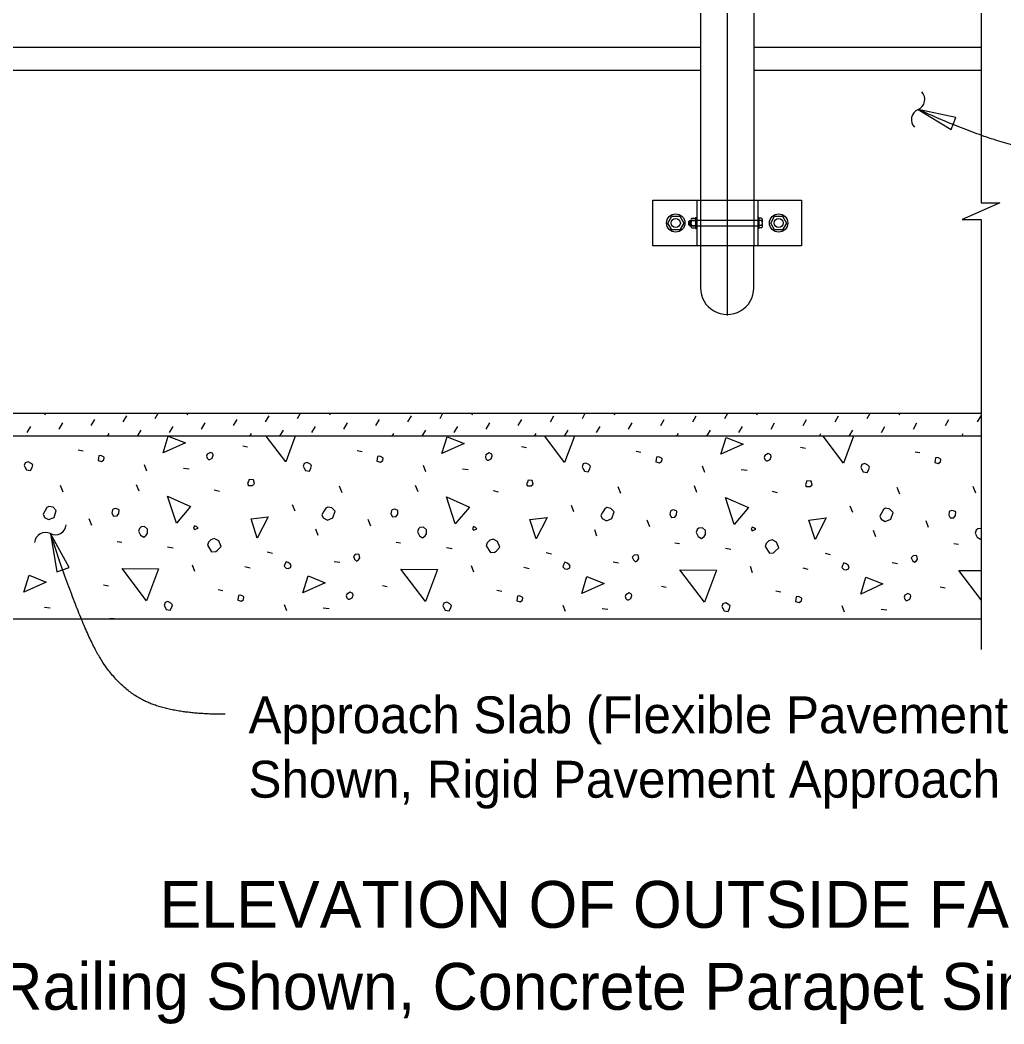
# Model space of a CAD drawing. Extents: x 0.2 to 40.8, y 0.5 to 25.7.
# Drawn here: x 10.75 to 16.13, y 10.89 to 16.37 of the extents above; entities that cross this region are included whole.
import ezdxf

# ---------------------------------------------------------------- set-up
doc = ezdxf.new("R2010")
doc.units = 0
for name, color, linetype in [('CL_Major', 7, 'Continuous'), ('Dimension', 7, 'Continuous'), ('Miscellaneous', 7, 'Continuous'), ('SteelMisc', 7, 'Continuous'), ('SteelMisc_h', 7, 'Continuous'), ('SupstrConc', 7, 'Continuous')]:
    doc.layers.add(name, color=color, linetype=linetype)

msp = doc.modelspace()

# ---------------------------------------------------------------- linework, layer by layer
at = {"layer": 'CL_Major'}
msp.add_line((14.615, 25.0052), (14.615, 14.7584), dxfattribs=at)
at = {"layer": 'Dimension'}
msp.add_lwpolyline([(16.002, 17.2246), (16.002, 15.3737), (16.1053, 15.3737), (16.002, 15.3287), (15.8987, 15.2837), (16.002, 15.2837), (16.002, 12.9339)], dxfattribs=at)
for points in [[(15.6583, 15.8852), (15.8392, 15.7761), (15.865, 15.8418)], [(10.9179, 13.5672), (10.9525, 13.3589), (11.0192, 13.3819)]]:
    msp.add_lwpolyline(points, close=True, dxfattribs=at)
for centre, start, end in [((15.6351, 15.9394), 292.7091, 44.4364), ((15.6811, 15.8294), 112.7091, 224.4364), ((10.944, 13.6201), 243.2317, 354.9589), ((10.8904, 13.5137), 63.2317, 174.9589)]:
    msp.add_arc(centre, 0.0596, start, end, dxfattribs=at)
for points in [[(16.9853, 15.6282), (16.9154, 15.6282), (16.2159, 15.6282), (15.6583, 15.8852)], [(11.8715, 12.5794), (11.6062, 12.5794), (11.3076, 12.7039), (11.092, 13.036), (10.9179, 13.5672)]]:
    msp.add_open_spline(points, degree=2, dxfattribs=at)
at = {"layer": 'Miscellaneous'}
for p, q in [((14.4075, 15.2575), (14.4075, 15.2696)), ((14.4132, 15.2575), (14.4132, 15.2696)), ((10.8876, 14.2162), (10.8924, 14.2245)), ((11.3154, 14.1773), (11.3349, 14.2109)), ((11.4904, 14.1967), (11.5065, 14.2245)), ((11.6655, 14.2162), (11.6703, 14.2245)), ((12.0933, 14.1773), (12.1127, 14.2109)), ((12.2683, 14.1967), (12.2843, 14.2245)), ((12.4433, 14.2162), (12.4481, 14.2245)), ((12.8711, 14.1773), (12.8905, 14.2109)), ((13.0461, 14.1967), (13.0621, 14.2245)), ((13.2211, 14.2162), (13.2259, 14.2245)), ((13.6489, 14.1773), (13.6683, 14.2109)), ((13.8239, 14.1967), (13.84, 14.2245)), ((13.9989, 14.2162), (14.0037, 14.2245)), ((14.4267, 14.1773), (14.4462, 14.2109)), ((14.6017, 14.1967), (14.6178, 14.2245)), ((14.7767, 14.2162), (14.7815, 14.2245)), ((15.2045, 14.1773), (15.224, 14.2109)), ((15.3795, 14.1967), (15.3956, 14.2245)), ((15.5545, 14.2162), (15.5593, 14.2245)), ((15.9823, 14.1773), (16.0018, 14.2109)), ((10.9654, 14.1384), (10.9849, 14.172)), ((11.1404, 14.1579), (11.1599, 14.1914)), ((11.7432, 14.1384), (11.7627, 14.172)), ((11.9182, 14.1579), (11.9377, 14.1914)), ((12.5211, 14.1384), (12.5405, 14.172)), ((12.6961, 14.1579), (12.7155, 14.1914)), ((13.2989, 14.1384), (13.3183, 14.172)), ((13.4739, 14.1579), (13.4933, 14.1914)), ((14.0767, 14.1384), (14.0961, 14.172)), ((14.2517, 14.1579), (14.2711, 14.1914)), ((14.8545, 14.1384), (14.874, 14.172)), ((15.0295, 14.1579), (15.049, 14.1914)), ((15.6323, 14.1384), (15.6518, 14.172)), ((15.8073, 14.1579), (15.8268, 14.1914)), ((10.7904, 14.119), (10.8099, 14.1526)), ((11.2295, 14.0995), (11.2377, 14.1137)), ((11.3932, 14.0995), (11.4127, 14.1331)), ((11.5682, 14.119), (11.5877, 14.1526)), ((12.0073, 14.0995), (12.0155, 14.1137)), ((12.171, 14.0995), (12.1905, 14.1331)), ((12.346, 14.119), (12.3655, 14.1526)), ((12.7851, 14.0995), (12.7933, 14.1137)), ((12.9489, 14.0995), (12.9683, 14.1331)), ((13.1239, 14.119), (13.1433, 14.1526)), ((13.5629, 14.0995), (13.5711, 14.1137)), ((13.7267, 14.0995), (13.7461, 14.1331)), ((13.9017, 14.119), (13.9211, 14.1526)), ((14.3407, 14.0995), (14.3489, 14.1137)), ((14.5045, 14.0995), (14.5239, 14.1331)), ((14.6795, 14.119), (14.6989, 14.1526)), ((15.1186, 14.0995), (15.1267, 14.1137)), ((15.2823, 14.0995), (15.3018, 14.1331)), ((15.4573, 14.119), (15.4768, 14.1526)), ((15.8964, 14.0995), (15.9046, 14.1137)), ((11.9679, 14.0465), (11.9945, 14.0412)), ((11.0699, 14.0253), (11.0964, 14.02)), ((12.5937, 14.0217), (12.6202, 14.0164)), ((13.4917, 14.043), (13.5183, 14.0376)), ((14.1175, 14.0182), (14.1441, 14.0129)), ((15.0156, 14.0394), (15.0421, 14.0341)), ((15.6414, 14.0147), (15.6679, 14.0094)), ((11.4447, 13.9086), (11.4323, 13.9422)), ((12.9685, 13.9051), (12.9561, 13.9387)), ((14.4923, 13.9015), (14.4799, 13.9351)), ((11.6444, 13.9245), (11.6763, 13.921)), ((13.1682, 13.921), (13.2001, 13.9174)), ((14.6921, 13.9174), (14.7239, 13.9139)), ((10.9868, 13.7937), (10.9727, 13.8291)), ((11.4022, 13.799), (11.3881, 13.8344)), ((12.5106, 13.7902), (12.4965, 13.8255)), ((12.9261, 13.7955), (12.9119, 13.8308)), ((14.4499, 13.7919), (14.4357, 13.8273)), ((11.8124, 13.8061), (11.8407, 13.799)), ((13.3362, 13.8025), (13.3645, 13.7955)), ((14.0345, 13.7866), (14.0203, 13.822)), ((14.86, 13.799), (14.8883, 13.7919)), ((15.5583, 13.7831), (15.5441, 13.8184)), ((15.9737, 13.7884), (15.9596, 13.8237)), ((12.2543, 13.6894), (12.2402, 13.7248)), ((13.7781, 13.6859), (13.764, 13.7212)), ((15.3019, 13.6823), (15.2878, 13.7177)), ((11.1442, 13.6116), (11.13, 13.647)), ((12.668, 13.6081), (12.6538, 13.6434)), ((14.1918, 13.6045), (14.1776, 13.6399)), ((15.7156, 13.601), (15.7015, 13.6364)), ((12.3798, 13.5568), (12.3675, 13.5904)), ((13.9036, 13.5533), (13.8913, 13.5869)), ((15.4275, 13.5497), (15.4151, 13.5833)), ((11.282, 13.5232), (11.3068, 13.5197)), ((12.8059, 13.5197), (12.8306, 13.5162)), ((14.3297, 13.5162), (14.3544, 13.5126)), ((15.8535, 13.5126), (15.8782, 13.5091)), ((11.5578, 13.4949), (11.5879, 13.4896)), ((12.1023, 13.4667), (12.1306, 13.4596)), ((13.0816, 13.4914), (13.1117, 13.4861)), ((13.6261, 13.4631), (13.6544, 13.4561)), ((14.6054, 13.4879), (14.6355, 13.4826)), ((15.1499, 13.4596), (15.1782, 13.4525)), ((11.7063, 13.3606), (11.6939, 13.3942)), ((11.9803, 13.3871), (12.0086, 13.38)), ((12.4682, 13.4154), (12.4983, 13.4101)), ((13.2301, 13.3571), (13.2177, 13.3906)), ((13.992, 13.4119), (14.0221, 13.4066)), ((14.7539, 13.3535), (14.7416, 13.3871)), ((15.5158, 13.4083), (15.5459, 13.403)), ((13.5041, 13.3836), (13.5324, 13.3765)), ((15.0279, 13.38), (15.0562, 13.373)), ((11.2078, 13.2863), (11.2343, 13.281)), ((12.7316, 13.2828), (12.7581, 13.2775)), ((14.2554, 13.2793), (14.2819, 13.274)), ((15.7792, 13.2757), (15.8058, 13.2704)), ((11.8336, 13.2616), (11.8601, 13.2563)), ((13.3574, 13.2581), (13.3839, 13.2528)), ((14.8812, 13.2545), (14.9077, 13.2492)), ((12.2084, 13.1449), (12.196, 13.1785)), ((13.7322, 13.1414), (13.7198, 13.175)), ((15.256, 13.1379), (15.2436, 13.1714)), ((10.8843, 13.1644), (10.9161, 13.1608)), ((12.4081, 13.1608), (12.4399, 13.1573)), ((13.9319, 13.1573), (13.9637, 13.1538)), ((15.4557, 13.1538), (15.4876, 13.1502))]:
    msp.add_line(p, q, dxfattribs=at)
for points in [[(11.5331, 14.0076), (11.5613, 14.0995), (11.655, 14.0624), (11.5331, 14.0076)], [(12.203, 13.9599), (12.0969, 14.0995)], [(12.2552, 14.0995), (12.203, 13.9599)], [(13.7269, 13.9563), (13.618, 14.0995)], [(13.7804, 14.0995), (13.7269, 13.9563)], [(15.2507, 13.9528), (15.1392, 14.0995)], [(15.3055, 14.0995), (15.2507, 13.9528)], [(13.0569, 14.0041), (13.0852, 14.096), (13.1789, 14.0589), (13.0569, 14.0041)], [(14.5807, 14.0005), (14.609, 14.0925), (14.7027, 14.0553), (14.5807, 14.0005)], [(11.1777, 13.9669), (11.1972, 13.9616), (11.2096, 13.9705), (11.2113, 13.9828), (11.2078, 13.9864), (11.1937, 13.9935), (11.1813, 13.9917), (11.1795, 13.9793), (11.1777, 13.9669)], [(11.7806, 13.9722), (11.7876, 13.9722), (11.8018, 13.9793), (11.8071, 13.9952), (11.8053, 14.0041), (11.7912, 14.0111), (11.7735, 14.0005), (11.7699, 13.9899), (11.7735, 13.9793), (11.7806, 13.9722)], [(12.7016, 13.9634), (12.721, 13.9581), (12.7334, 13.9669), (12.7351, 13.9793), (12.7316, 13.9828), (12.7175, 13.9899), (12.7051, 13.9882), (12.7033, 13.9758), (12.7016, 13.9634)], [(13.3044, 13.9687), (13.3114, 13.9687), (13.3256, 13.9758), (13.3309, 13.9917), (13.3291, 14.0005), (13.315, 14.0076), (13.2973, 13.997), (13.2938, 13.9864), (13.2973, 13.9758), (13.3044, 13.9687)], [(14.8282, 13.9652), (14.8353, 13.9652), (14.8494, 13.9722), (14.8547, 13.9882), (14.8529, 13.997), (14.8388, 14.0041), (14.8211, 13.9935), (14.8176, 13.9828), (14.8211, 13.9722), (14.8282, 13.9652)], [(10.7782, 13.9316), (10.7871, 13.9157), (10.8083, 13.9121), (10.8171, 13.928), (10.8207, 13.9422), (10.8118, 13.951), (10.7959, 13.9599), (10.78, 13.9546), (10.7747, 13.9387), (10.7782, 13.9316)], [(12.302, 13.928), (12.3109, 13.9121), (12.3321, 13.9086), (12.3409, 13.9245), (12.3445, 13.9387), (12.3356, 13.9475), (12.3197, 13.9563), (12.3038, 13.951), (12.2985, 13.9351), (12.302, 13.928)], [(13.8259, 13.9245), (13.8347, 13.9086), (13.8559, 13.9051), (13.8647, 13.921), (13.8683, 13.9351), (13.8594, 13.944), (13.8435, 13.9528), (13.8276, 13.9475), (13.8223, 13.9316), (13.8259, 13.9245)], [(14.2254, 13.9599), (14.2448, 13.9546), (14.2572, 13.9634), (14.259, 13.9758), (14.2554, 13.9793), (14.2413, 13.9864), (14.2289, 13.9846), (14.2271, 13.9722), (14.2254, 13.9599)], [(15.3497, 13.921), (15.3585, 13.9051), (15.3797, 13.9015), (15.3886, 13.9174), (15.3921, 13.9316), (15.3833, 13.9404), (15.3674, 13.9493), (15.3514, 13.944), (15.3461, 13.928), (15.3497, 13.921)], [(15.7492, 13.9563), (15.7686, 13.951), (15.781, 13.9599), (15.7828, 13.9722), (15.7792, 13.9758), (15.7651, 13.9828), (15.7527, 13.9811), (15.751, 13.9687), (15.7492, 13.9563)], [(11.9998, 13.8308), (12.021, 13.8308), (12.0316, 13.8414), (12.0263, 13.8609), (12.0033, 13.8626), (11.9998, 13.852), (11.9945, 13.8432), (11.9998, 13.8308), (11.9962, 13.8344)], [(13.5236, 13.8273), (13.5448, 13.8273), (13.5554, 13.8379), (13.5501, 13.8573), (13.5271, 13.8591), (13.5236, 13.8485), (13.5183, 13.8397), (13.5236, 13.8273), (13.52, 13.8308)], [(15.0474, 13.8237), (15.0686, 13.8237), (15.0792, 13.8344), (15.0739, 13.8538), (15.0509, 13.8556), (15.0474, 13.845), (15.0421, 13.8361), (15.0474, 13.8237), (15.0438, 13.8273)], [(11.6055, 13.624), (11.5578, 13.7707), (11.6833, 13.7159), (11.6055, 13.624)], [(10.8843, 13.6558), (10.9073, 13.6434), (10.9373, 13.6558), (10.9497, 13.6929), (10.932, 13.7106), (10.909, 13.7159), (10.8984, 13.7088), (10.8861, 13.6894), (10.8772, 13.6735), (10.8843, 13.6558)], [(13.1294, 13.6205), (13.0816, 13.7672), (13.2071, 13.7124), (13.1294, 13.6205)], [(14.6532, 13.6169), (14.6054, 13.7636), (14.731, 13.7088), (14.6532, 13.6169)], [(11.2538, 13.6788), (11.2626, 13.6629), (11.282, 13.6647), (11.2909, 13.677), (11.2926, 13.6965), (11.2803, 13.7018), (11.2714, 13.7035), (11.2608, 13.7), (11.2573, 13.6965), (11.2538, 13.6788)], [(12.4081, 13.6523), (12.4311, 13.6399), (12.4611, 13.6523), (12.4735, 13.6894), (12.4558, 13.7071), (12.4329, 13.7124), (12.4223, 13.7053), (12.4099, 13.6859), (12.401, 13.67), (12.4081, 13.6523)], [(12.7776, 13.6753), (12.7864, 13.6593), (12.8059, 13.6611), (12.8147, 13.6735), (12.8165, 13.6929), (12.8041, 13.6982), (12.7952, 13.7), (12.7846, 13.6965), (12.7811, 13.6929), (12.7776, 13.6753)], [(13.9319, 13.6487), (13.9549, 13.6364), (13.985, 13.6487), (13.9973, 13.6859), (13.9797, 13.7035), (13.9567, 13.7088), (13.9461, 13.7018), (13.9337, 13.6823), (13.9249, 13.6664), (13.9319, 13.6487)], [(14.3014, 13.6717), (14.3102, 13.6558), (14.3297, 13.6576), (14.3385, 13.67), (14.3403, 13.6894), (14.3279, 13.6947), (14.3191, 13.6965), (14.3085, 13.6929), (14.3049, 13.6894), (14.3014, 13.6717)], [(15.4557, 13.6452), (15.4787, 13.6328), (15.5088, 13.6452), (15.5211, 13.6823), (15.5035, 13.7), (15.4805, 13.7053), (15.4699, 13.6982), (15.4575, 13.6788), (15.4487, 13.6629), (15.4557, 13.6452)], [(15.8252, 13.6682), (15.834, 13.6523), (15.8535, 13.654), (15.8623, 13.6664), (15.8641, 13.6859), (15.8517, 13.6912), (15.8429, 13.6929), (15.8323, 13.6894), (15.8287, 13.6859), (15.8252, 13.6682)], [(11.3987, 13.5798), (11.4093, 13.5586), (11.427, 13.548), (11.4411, 13.5586), (11.4482, 13.5692), (11.4482, 13.5904), (11.4323, 13.6063), (11.4129, 13.6045), (11.404, 13.5957), (11.3987, 13.5798)], [(11.7045, 13.5886), (11.724, 13.5975), (11.7169, 13.6045), (11.7045, 13.6098), (11.6992, 13.5975), (11.7045, 13.5886)], [(12.0475, 13.5427), (12.0139, 13.647), (12.1076, 13.6593), (12.0475, 13.5427)], [(13.2284, 13.5851), (13.2478, 13.5939), (13.2407, 13.601), (13.2284, 13.6063), (13.223, 13.5939), (13.2284, 13.5851)], [(13.5713, 13.5391), (13.5377, 13.6434), (13.6314, 13.6558), (13.5713, 13.5391)], [(15.0951, 13.5356), (15.0615, 13.6399), (15.1552, 13.6523), (15.0951, 13.5356)], [(12.9225, 13.5763), (12.9331, 13.555), (12.9508, 13.5444), (12.965, 13.555), (12.972, 13.5657), (12.972, 13.5869), (12.9561, 13.6028), (12.9367, 13.601), (12.9278, 13.5922), (12.9225, 13.5763)], [(14.4463, 13.5727), (14.457, 13.5515), (14.4746, 13.5409), (14.4888, 13.5515), (14.4958, 13.5621), (14.4958, 13.5833), (14.4799, 13.5992), (14.4605, 13.5975), (14.4516, 13.5886), (14.4463, 13.5727)], [(14.7522, 13.5816), (14.7716, 13.5904), (14.7645, 13.5975), (14.7522, 13.6028), (14.7469, 13.5904), (14.7522, 13.5816)], [(16.002, 13.5955), (15.9843, 13.5939), (15.9755, 13.5851), (15.9702, 13.5692)], [(15.9702, 13.5692), (15.9808, 13.548), (15.9984, 13.5374), (16.002, 13.54)], [(11.7752, 13.5038), (11.7982, 13.4667), (11.8212, 13.4684), (11.83, 13.4773), (11.8495, 13.4967), (11.8371, 13.5268), (11.8124, 13.5409), (11.7947, 13.5338), (11.7806, 13.5197), (11.7752, 13.5038)], [(13.2991, 13.5002), (13.322, 13.4631), (13.345, 13.4649), (13.3539, 13.4737), (13.3733, 13.4932), (13.3609, 13.5232), (13.3362, 13.5374), (13.3185, 13.5303), (13.3044, 13.5162), (13.2991, 13.5002)], [(14.8229, 13.4967), (14.8459, 13.4596), (14.8688, 13.4614), (14.8777, 13.4702), (14.8971, 13.4896), (14.8848, 13.5197), (14.86, 13.5338), (14.8423, 13.5268), (14.8282, 13.5126), (14.8229, 13.4967)], [(12.5796, 13.4278), (12.5902, 13.4172), (12.6008, 13.4242), (12.6079, 13.4348), (12.6043, 13.4525), (12.5955, 13.4543), (12.5831, 13.4525), (12.5725, 13.4419), (12.5796, 13.4278)], [(14.1034, 13.4242), (14.114, 13.4136), (14.1246, 13.4207), (14.1317, 13.4313), (14.1281, 13.449), (14.1193, 13.4508), (14.1069, 13.449), (14.0963, 13.4384), (14.1034, 13.4242)], [(15.6272, 13.4207), (15.6378, 13.4101), (15.6484, 13.4172), (15.6555, 13.4278), (15.652, 13.4454), (15.6431, 13.4472), (15.6307, 13.4454), (15.6201, 13.4348), (15.6272, 13.4207)], [(12.2048, 13.3783), (12.2172, 13.3765), (12.2296, 13.3818), (12.2331, 13.3924), (12.2278, 13.4013), (12.2172, 13.4083), (12.2048, 13.4136), (12.1977, 13.3995), (12.1942, 13.3889), (12.2048, 13.3783)], [(13.7286, 13.3747), (13.741, 13.373), (13.7534, 13.3783), (13.7569, 13.3889), (13.7516, 13.3977), (13.741, 13.4048), (13.7286, 13.4101), (13.7216, 13.3959), (13.718, 13.3853), (13.7286, 13.3747)], [(15.2524, 13.3712), (15.2648, 13.3694), (15.2772, 13.3747), (15.2807, 13.3853), (15.2754, 13.3942), (15.2648, 13.4013), (15.2524, 13.4066), (15.2454, 13.3924), (15.2418, 13.3818), (15.2524, 13.3712)], [(10.7729, 13.2475), (10.8012, 13.3394), (10.8949, 13.3023), (10.7729, 13.2475)], [(11.4429, 13.1997), (11.3086, 13.3765), (11.5083, 13.3747), (11.4429, 13.1997)], [(12.2967, 13.2439), (12.325, 13.3358), (12.4187, 13.2987), (12.2967, 13.2439)], [(12.9667, 13.1962), (12.8324, 13.373), (13.0321, 13.3712), (12.9667, 13.1962)], [(13.8206, 13.2404), (13.8488, 13.3323), (13.9425, 13.2952), (13.8206, 13.2404)], [(14.4905, 13.1927), (14.3562, 13.3694), (14.5559, 13.3677), (14.4905, 13.1927)], [(16.002, 13.2054), (15.88, 13.3659), (16.002, 13.3648)], [(15.3444, 13.2369), (15.3727, 13.3288), (15.4663, 13.2917), (15.3444, 13.2369)], [(11.9414, 13.2033), (11.9609, 13.198), (11.9732, 13.2068), (11.975, 13.2192), (11.9715, 13.2227), (11.9573, 13.2298), (11.945, 13.228), (11.9432, 13.2156), (11.9414, 13.2033)], [(12.5442, 13.2086), (12.5513, 13.2086), (12.5654, 13.2156), (12.5707, 13.2315), (12.569, 13.2404), (12.5548, 13.2475), (12.5372, 13.2369), (12.5336, 13.2262), (12.5372, 13.2156), (12.5442, 13.2086)], [(13.4652, 13.1997), (13.4847, 13.1944), (13.4971, 13.2033), (13.4988, 13.2156), (13.4953, 13.2192), (13.4811, 13.2262), (13.4688, 13.2245), (13.467, 13.2121), (13.4652, 13.1997)], [(14.068, 13.205), (14.0751, 13.205), (14.0893, 13.2121), (14.0946, 13.228), (14.0928, 13.2369), (14.0786, 13.2439), (14.061, 13.2333), (14.0574, 13.2227), (14.061, 13.2121), (14.068, 13.205)], [(14.989, 13.1962), (15.0085, 13.1909), (15.0209, 13.1997), (15.0226, 13.2121), (15.0191, 13.2156), (15.005, 13.2227), (14.9926, 13.2209), (14.9908, 13.2086), (14.989, 13.1962)], [(15.5919, 13.2015), (15.5989, 13.2015), (15.6131, 13.2086), (15.6184, 13.2245), (15.6166, 13.2333), (15.6025, 13.2404), (15.5848, 13.2298), (15.5813, 13.2192), (15.5848, 13.2086), (15.5919, 13.2015)], [(11.5419, 13.1679), (11.5507, 13.152), (11.572, 13.1485), (11.5808, 13.1644), (11.5843, 13.1785), (11.5755, 13.1874), (11.5596, 13.1962), (11.5437, 13.1909), (11.5384, 13.175), (11.5419, 13.1679)], [(13.0657, 13.1644), (13.0746, 13.1485), (13.0958, 13.1449), (13.1046, 13.1608), (13.1081, 13.175), (13.0993, 13.1838), (13.0834, 13.1927), (13.0675, 13.1874), (13.0622, 13.1714), (13.0657, 13.1644)], [(14.5895, 13.1608), (14.5984, 13.1449), (14.6196, 13.1414), (14.6284, 13.1573), (14.632, 13.1714), (14.6231, 13.1803), (14.6072, 13.1891), (14.5913, 13.1838), (14.586, 13.1679), (14.5895, 13.1608)], [(11.2665, 13.0995), (11.2661, 13.1007), (11.2432, 13.1025), (11.2422, 13.0995)]]:
    msp.add_lwpolyline(points, dxfattribs=at)
at = {"layer": 'SteelMisc'}
for p, q in [((14.4692, 16.6394), (14.4692, 15.3894)), ((14.7609, 16.6394), (14.7609, 15.3894)), ((14.2091, 15.3894), (15.021, 15.3894)), ((14.2091, 15.1394), (14.2091, 15.3894)), ((14.4484, 15.3894), (14.4484, 15.1394)), ((14.7817, 15.3894), (14.7817, 15.1394)), ((15.021, 15.3894), (15.021, 15.1394)), ((14.4047, 15.2724), (14.4103, 15.2789)), ((14.4047, 15.2547), (14.4047, 15.2724)), ((14.4047, 15.2547), (14.4103, 15.249)), ((14.4103, 15.2789), (14.4168, 15.2789)), ((14.4103, 15.249), (14.4103, 15.2789)), ((14.4168, 15.2823), (14.4168, 15.2465)), ((14.4215, 15.2774), (14.4418, 15.2774)), ((14.4215, 15.2514), (14.4418, 15.2514)), ((14.4217, 15.2904), (14.4418, 15.2904)), ((14.4418, 15.2947), (14.4418, 15.234)), ((14.4418, 15.2947), (14.4484, 15.2947)), ((14.4418, 15.2904), (14.4418, 15.2384)), ((14.788, 15.2947), (14.782, 15.2947)), ((14.788, 15.2947), (14.788, 15.234)), ((14.8027, 15.2903), (14.788, 15.2903)), ((14.8028, 15.2773), (14.788, 15.2773)), ((14.8028, 15.2514), (14.788, 15.2514)), ((14.8078, 15.245), (14.8078, 15.2838)), ((14.4103, 15.249), (14.4168, 15.249)), ((14.4218, 15.2384), (14.4418, 15.2384)), ((14.4418, 15.234), (14.4484, 15.234)), ((14.788, 15.234), (14.782, 15.234)), ((14.8027, 15.2384), (14.788, 15.2384)), ((15.021, 15.1394), (14.2091, 15.1394)), ((14.4691, 15.1394), (14.4691, 14.9102)), ((14.7608, 14.9102), (14.7608, 15.1394))]:
    msp.add_line(p, q, dxfattribs=at)
for points in [[(14.3124, 15.3019), (14.3557, 15.3019), (14.3774, 15.2644), (14.3557, 15.2269), (14.3124, 15.2269), (14.2907, 15.2644)], [(14.8744, 15.3019), (14.9177, 15.3019), (14.9394, 15.2644), (14.9177, 15.2269), (14.8744, 15.2269), (14.8527, 15.2644)]]:
    msp.add_lwpolyline(points, close=True, dxfattribs=at)
for centre, radius in [((14.3341, 15.2644), 0.05), ((14.896, 15.2644), 0.05), ((14.3341, 15.2644), 0.025), ((14.896, 15.2644), 0.025)]:
    msp.add_circle(centre, radius, dxfattribs=at)
for centre, radius, start, end in [((14.4234, 15.2838), 0.00674, 104.4891, 254.1889), ((14.4363, 15.2644), 0.0196, 138.628, 221.372), ((14.4234, 15.2449), 0.00673, 105.7823, 255.5404), ((14.801, 15.2838), 0.00673, 285.7823, 75.5404), ((14.801, 15.2449), 0.00674, 284.4891, 74.1889), ((14.7881, 15.2644), 0.0196, 318.628, 41.372)]:
    msp.add_arc(centre, radius, start, end, dxfattribs=at)
msp.add_ellipse((14.615, 14.9102), major_axis=(0, 0.1458), ratio=0.999499, start_param=1.570796, end_param=4.712389, dxfattribs=at)
at = {"layer": 'SteelMisc_h'}
for p, q in [((14.4692, 15.3894), (14.4692, 15.1394)), ((14.7609, 15.3894), (14.7609, 15.1394)), ((14.7817, 15.2789), (14.4168, 15.2789)), ((14.4168, 15.249), (14.7817, 15.249))]:
    msp.add_line(p, q, dxfattribs=at)
at = {"layer": 'SupstrConc'}
for p, q in [((4.7609, 16.2245), (14.4692, 16.2245)), ((14.7609, 16.2245), (16.002, 16.2245)), ((4.7609, 16.0995), (14.4692, 16.0995)), ((14.7609, 16.0995), (16.002, 16.0995)), ((3.615, 14.2245), (16.002, 14.2245)), ((16.002, 14.0995), (3.615, 14.0995)), ((16.002, 13.0995), (3.615, 13.0995))]:
    msp.add_line(p, q, dxfattribs=at)

# ---------------------------------------------------------------- texts
at = {"layer": 'Dimension'}
for s, height, p in [('Approach Slab (Flexible Pavement Approach Slab ', 0.2016, (11.9999, 12.4759)), ('Shown, Rigid Pavement Approach Slab Similar)', 0.2016, (11.9999, 12.1239)), ('ELEVATION OF OUTSIDE FACE OF RAILING', 0.256001, (11.5134, 11.4128)), ('(Traffic Railing Shown, Concrete Parapet Similar) (See Note 3)', 0.256001, (9.4668, 10.9648))]:
    msp.add_text(s, height=height, dxfattribs=at).set_placement(p)

doc.saveas('drawing.dxf')
